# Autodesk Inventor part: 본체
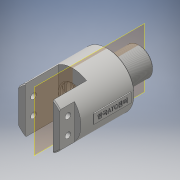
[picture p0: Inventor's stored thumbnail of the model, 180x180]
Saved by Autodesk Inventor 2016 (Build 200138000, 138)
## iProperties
Created: 2019-02
Part Number: 본체
Material: 일반
Document SubType Name: Modeling
Designer: USER
Density: 1 g/cm^3
Appearance: 기본값
Author: USER
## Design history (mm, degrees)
sketch "스케치1"
  geometry: C1 r 29 at (0, 0); 1 further point
  constraints: 1 centre point, 1 coincident
  dimensions: "d0" = 58 diameter of C1
extrude "돌출1" new body sketch "스케치1" distance "d1" = 74; taper "d2" = 0 deg
sketch "스케치2"
  geometry: C1 r 29 at (0, 0) reference; C2 r 13 at (0, 0); 1 further point
  constraints: 1 centre point, 1 coincident
  dimensions: "d3" = 26 diameter of C2
extrude "돌출2" join sketch "스케치2" distance "d4" = 5; taper "d5" = 0 deg
sketch "스케치3"
  geometry: C1 r 13 at (0, 0) reference; C2 r 15 at (0, 0); 1 further point
  constraints: 1 centre point, 1 coincident
  dimensions: "d6" = 30 diameter of C2
extrude "돌출3" join sketch "스케치3" distance "d7" = 29; taper "d8" = 0 deg
node "작업 평면1"
sketch "스케치4"
  geometry: L1 (0, 0)-(0, 36); L2 (-15, 0)-(-15, 36); L3 (15, 0)-(15, 36); L4 (-15, 36)-(15, 36); L5 (-15, 0)-(15, 0); L6 (-29, 0)-(29, 0) reference; L7 (29, 74)-(-29, 74) reference; L8 (-29, 0)-(29, 0) reference; L9 (-29, 0)-(-29, 74) reference
  constraints: 10 end point, 2 parallel, 1 collinear, 1 horizontal, 1 vertical
  dimensions: "d10" = 36 distance of L1.start L1.end; "d11" = 15 distance between parallel lines of L1 L2; "d12" = 15 distance between parallel lines of L1 L3; "d13" = 36 distance between parallel lines of L5 L4; "d14" = 38 distance between parallel lines of L7 L4
extrude "돌출4" cut sketch "스케치4" stored distance "d15" = 80; taper "d16" = 0 deg
sketch "스케치5"
  geometry: L1 (0, 0)-(0, 16); L2 (-22, 0)-(-22, 16); L3 (22, 0)-(22, 16); L4 (-22, 16)-(-29, 16); L5 (-29, 0)-(-29, 74) reference; L6 (-29, 0)-(-15, 0) reference; L7 (-22, 0)-(-29, 0); L8 (-29, 0)-(-29, 16); L9 (15, 0)-(29, 0) reference; L10 (22, 0)-(29, 0); L11 (22, 16)-(29, 16); L12 (29, 16)-(29, 0)
  constraints: 18 end point, 3 horizontal, 2 collinear, 2 parallel, 1 perpendicular, 1 point on line, 1 vertical
  dimensions: "d17" = 16 distance of L1.start L1.end; "d18" = 22 distance between parallel lines of L1 L2; "d19" = 22 distance between parallel lines of L1 L3; "d20" = 16 distance between parallel lines of L6 L4; "d21" = 16 distance between parallel lines of L9 L11
extrude "돌출5" cut sketch "스케치5" stored distance "d22" = 80; taper "d23" = 0 deg
node "작업 평면2"
sketch "스케치6"
  geometry: L1 (108, -15)-(108, 15) reference; L2 (108, 0)-(36, 0); L3 (36, 24.819)-(36, -24.819) reference; L4 (108, 0)-(108, 7); L5 (36, 0)-(36, 14); L6 (108, 7)-(86, 7); L7 (108, 0)-(108, 4); L8 (86, 4)-(63, 4); L9 (86, 7)-(86, 4); L10 (63, 4)-(63, 16); L11 (63, 16)-(56, 16); L12 (56, 16)-(56, 14); L13 (56, 14)-(52.35, 14); L14 (52.35, 17)-(52.35, 14); L15 (47.65, 17)-(47.65, 14); L16 (52.35, 17)-(47.65, 17); L17 (36, 14)-(38.65, 14); L18 (43.35, 14)-(43.35, 17); L19 (38.65, 14)-(38.65, 17); L20 (43.35, 14)-(47.65, 14); L21 (38.65, 17)-(43.35, 17); L22 (36, 29)-(74, 29) reference; 1 further point
  constraints: 38 end point, 6 perpendicular, 4 point on line, 3 horizontal, 2 midpoint, 1 vertical
  dimensions: "d25" = 7 distance of L2.start L4.end; "d32" = 22 distance of L4.end L6.end; "d33" = 4 distance of L2.start L7.end; "d34" = 23 distance of L8.start L8.end; "d35" = 3 distance of L6.end L8.start; "d37" = 7 distance of L10.end L11.end; "d38" = 2 distance of L11.end L12.end; "d42" = 3 distance of L13.end L14.start; "d44" = 3 distance of L15.start L15.end; "d52" = 4.7 distance of L19.end L18.end; "d53" = 4.7 distance of L14.start L15.start; "d54" = 28 diameter of L17 L2; "d55" = 34 diameter of L21 L2; "d56" = 32 diameter of L11 L2; "d57" = 4.3 distance of L18.start L15.end; "d58" = 3 distance of L18.start L18.end; "d60" = 12 distance between parallel lines of L22 L16; "d61" = 2.65 distance between parallel lines of L19 L3; "d62" = 3.65 distance of L12.end L13.end
revolve "회전1" sketch "스케치6" stored, may be unused: angle "d63" = 90 deg
sketch "스케치7"
  geometry: L1 (0, 0)-(-37.789, 0) reference; L2 (-18.894, 0)-(-18.894, 16); L3 (0, 16)-(-37.789, 16) reference; C1 r 3 at (-9.894, 9); C2 r 3 at (-27.894, 9)
  constraints: 2 centre point, 2 end point, 1 midpoint
  dimensions: "d64" = 6 diameter of C1; "d65" = 6 diameter of C2; "d66" = 9 distance from line of L1 C1.centre; "d67" = 9 distance from line of L1 C2.centre; "d68" = 9 distance from line of L2 C1.centre; "d69" = 9 distance from line of L2 C2.centre
extrude "돌출6" cut sketch "스케치7" distance "d70" = 50; taper "d71" = 0 deg
chamfer "모따기1" distance "d72" = 1; stored, may be unused: second distance "d73" = 2, angle "d74" = 45 deg
chamfer "모따기2" distance "d75" = 1; stored, may be unused: second distance "d76" = 2, angle "d77" = 45 deg
chamfer "모따기3" distance "d78" = 1; stored, may be unused: second distance "d79" = 2, angle "d80" = 45 deg
chamfer "모따기4" distance "d81" = 1; stored, may be unused: second distance "d82" = 2, angle "d83" = 45 deg
fillet "모깎기1" dims "d84" = 3
chamfer "모따기5" distance "d85" = 1; stored, may be unused: second distance "d86" = 2, angle "d87" = 45 deg
feature "스레드1" dims "d88" = 29, "d89" = 0
fillet "모깎기2" dims "d90" = 0.8
fillet "모깎기3" dims "d91" = 0.8
node "작업 평면3"
fillet "모깎기4" dims "d97" = 0.8
sketch "스케치9"
  geometry: L1 (29, -5)-(69, -5); L2 (69, -5)-(69, 5); L3 (69, 5)-(29, 5); L4 (29, 5)-(29, -5); L5 (69, 0)-(29, 0); L6 (74, 28)-(74, -28) reference; 1 further point
  constraints: 10 end point, 2 midpoint, 2 parallel, 1 horizontal, 1 horizontal alignment, 1 perpendicular
  dimensions: "d104" = 10 distance of L3.end L1.start; "d105" = 40 distance of L2.end L3.end; "d106" = 5 distance between parallel lines of L6 L2
extrude "돌출7" join sketch "스케치9" distance "d107" = 1; taper "d108" = 0 deg
node "작업 평면4"
sketch "스케치10"
  geometry: L1 (69, 5)-(29, 5) reference; L2 (29, 5)-(29, -5) reference; 2 further points
  constraints: 1 other
  dimensions: "d110" = 5 distance from line of L1 point (49, 0); "d111" = 20 distance from line of L2 point (49, 0)
feature "엠보싱2" sketch "스케치10" dims "d10" = 36, "d11" = 15, "d12" = 15, "d13" = 36, "d14" = 38, "d112" = 0.5, "d113" = 0
chamfer "모따기9" distance "d120" = 1; stored, may be unused: second distance "d121" = 2, angle "d122" = 45 deg
feature "스레드2" dims "d123" = 14, "d124" = 0
node "솔리드1"
node "투영된 루프1"
node "투영된 루프2"
node "투영된 루프3"
other parameters: "d9" = 0, "d24" = 0, "d95" = 29
